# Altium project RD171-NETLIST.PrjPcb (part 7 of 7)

## Sheet 8.SchDoc
size 420 x 297 mm
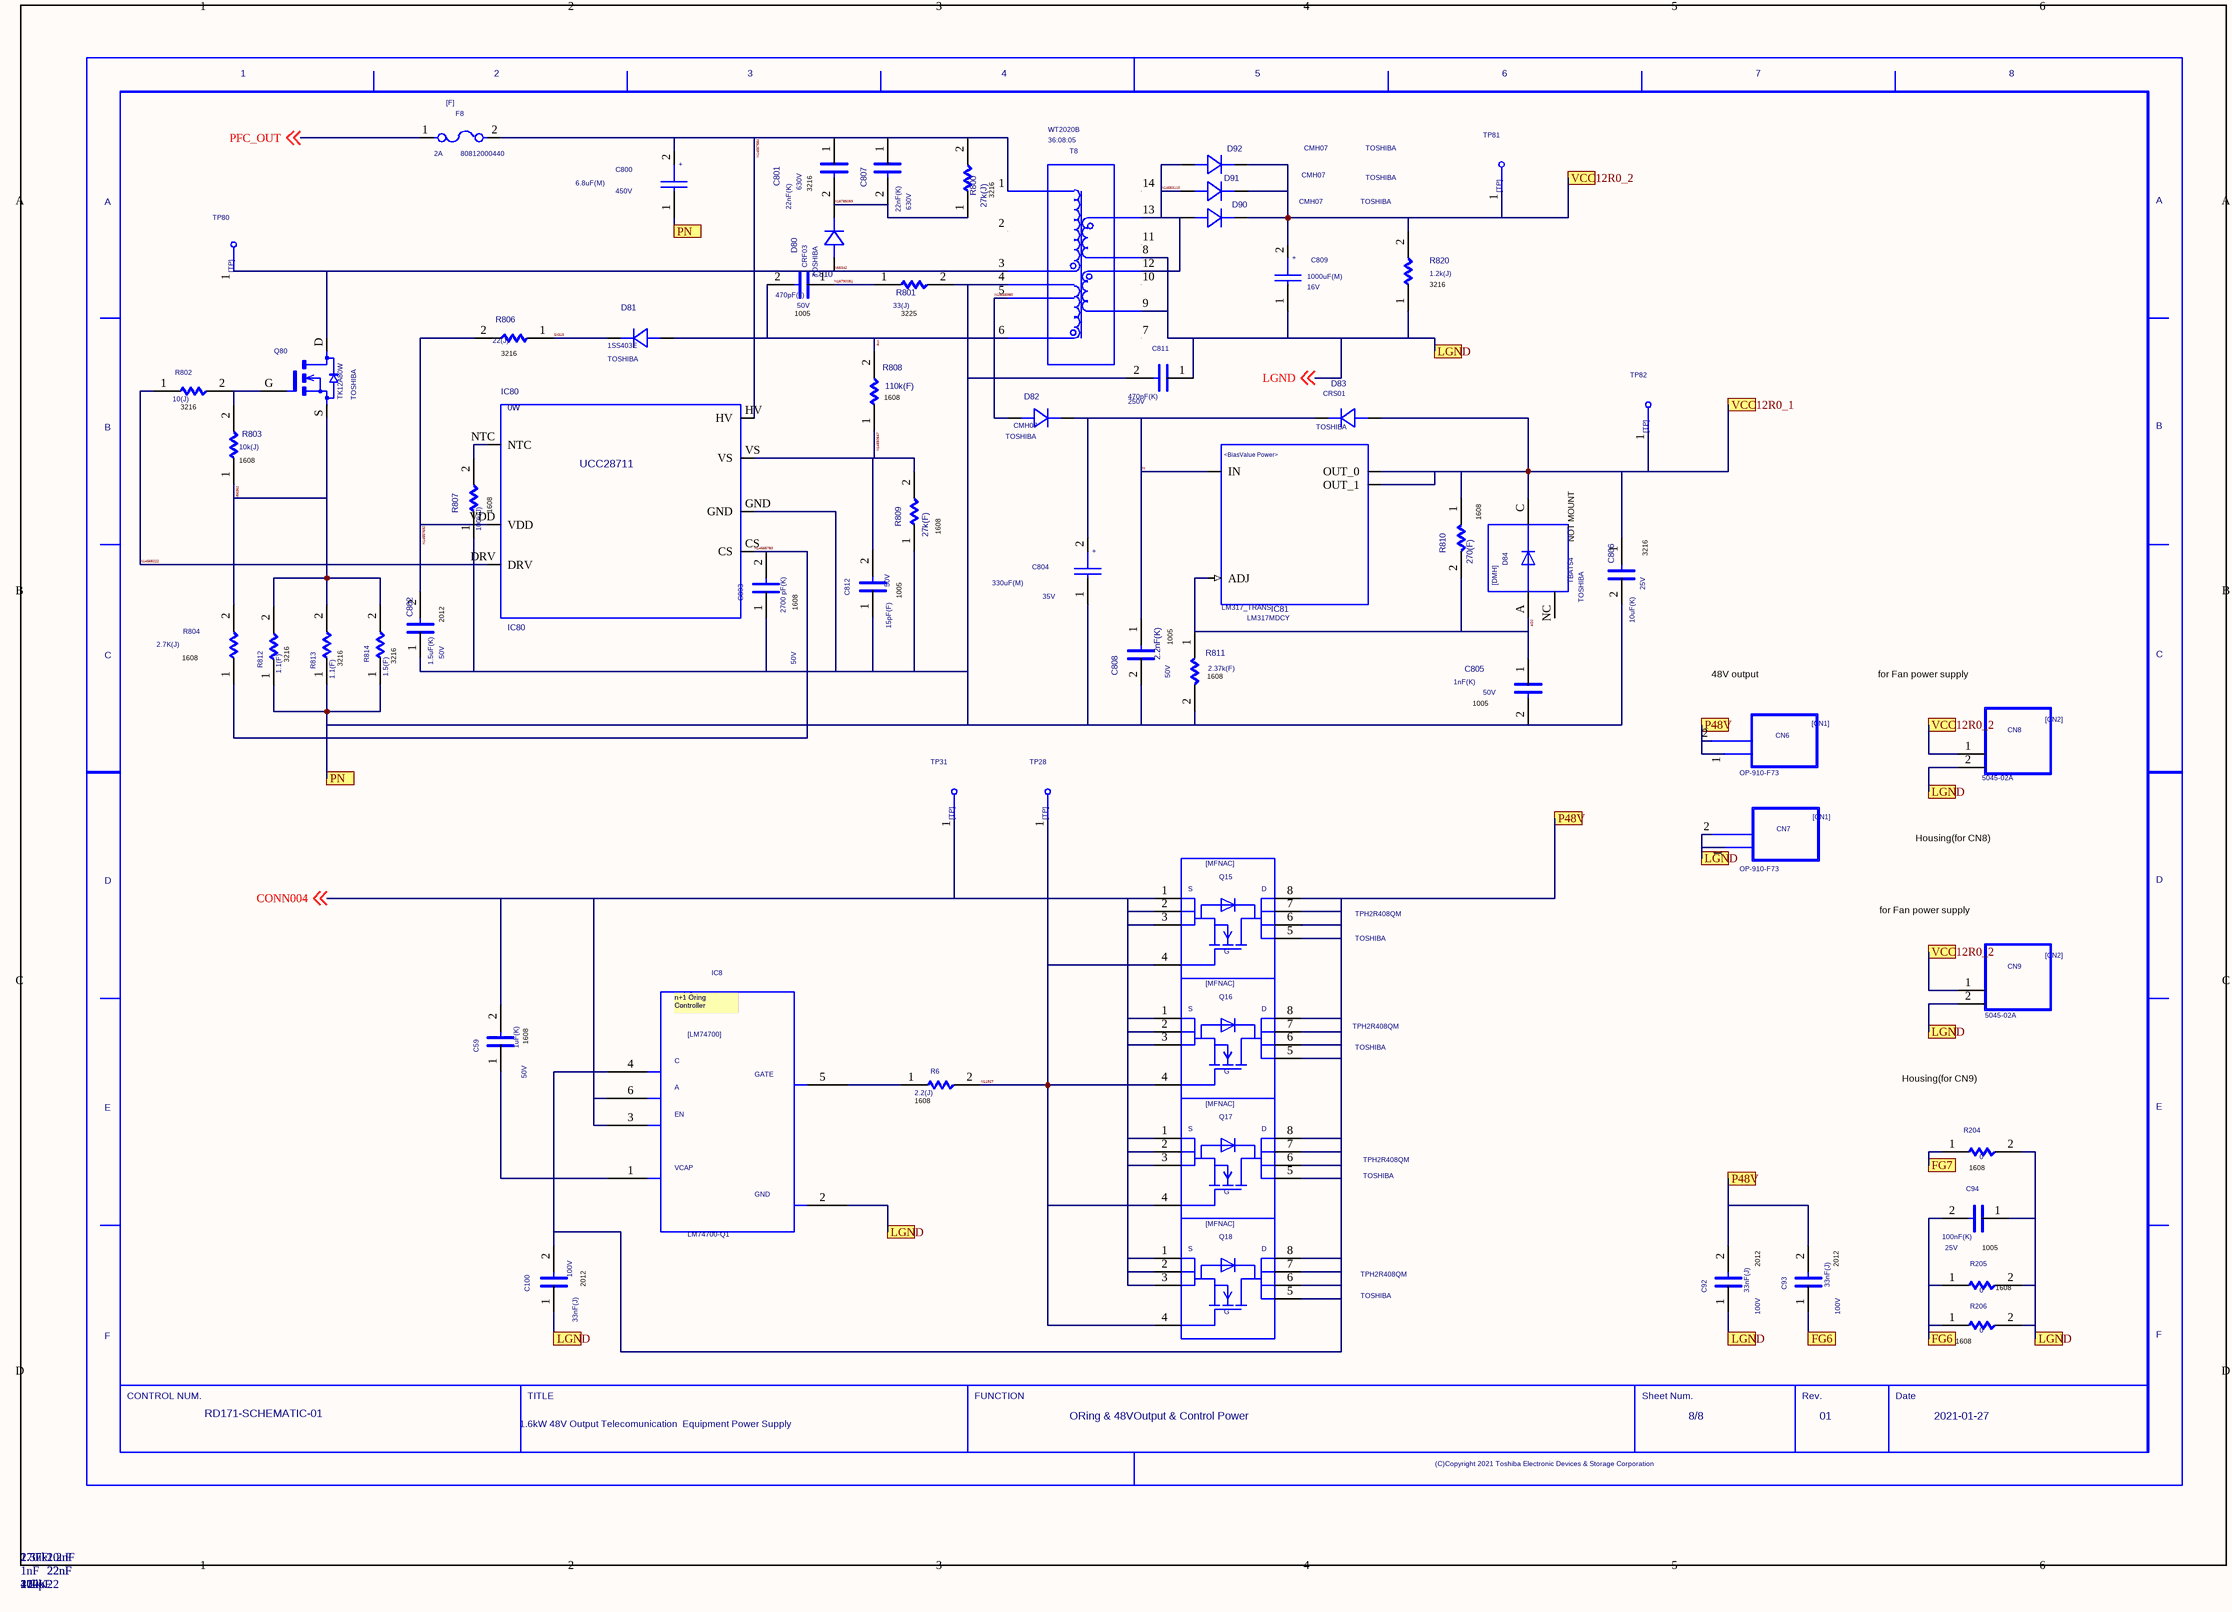
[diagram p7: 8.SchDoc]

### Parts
(Parts that share a designator on the sheet are numbered #1, #2 ... from top to bottom, then left to right.)
C59  VAL2: 50V  VAL1: 1uF(K)  [C1608JB1H105K080AB]  (hidden comment: 1uF)
C92  VAL2: 100V  VAL1: 33nF(J)  [C2012C0G2A333J125AE]  (hidden comment: 33nF)
C93  VAL2: 100V  VAL1: 33nF(J)  [C2012C0G2A333J125AE]  (hidden comment: 33nF)
C94  VAL2: 25V  VAL1: 100nF(K)  (hidden comment: 100nF)
C100  VAL2: 100V  VAL1: 33nF(J)  [C2012C0G2A333J125AE]  (hidden comment: 33nF)
C800  VAL2: 450V  VAL1: 6.8uF(M)  [EKXJ451ETD6R8MJ16S]  (hidden comment: 6.8uF)
C801  VAL2: 630V  VAL1: 22nF(K)  [C3216X7R2J223K130AA]  (hidden comment: 22nF)
C802  VAL2: 50V  VAL1: 1.5uF(K)  [C2012X7R1H155K125AC]  (hidden comment: 1.5uF)
C803  VAL2: 50V  VAL1: 2700 pF(K)  (hidden comment: 2.7nF)
C804  VAL2: 35V  VAL1: 330uF(M)  [EKZH350ETD331MJC5S]  (hidden comment: 330uF)
C805  VAL2: 50V  VAL1: 1nF(K)  (hidden comment: 1nF)
C806  VAL2: 25V  VAL1: 10uF(K)  [C3216X7R1E106K160AE]  (hidden comment: 10uF)
C807  VAL2: 630V  VAL1: 22nF(K)  [C3216X7R2J223K130AA]  (hidden comment: 22nF)
C808  VAL2: 50V  VAL1: 2.2nF(K)  (hidden comment: 2.2nF)
C809  VAL2: 16V  VAL1: 1000uF(M)  [EKZH160ELL102MH20D]  (hidden comment: 1000uF)
C810  VAL2: 50V  VAL1: 470pF(J)  [C1005NP01H471J050BA]  (hidden comment: 470pF)
C811  VAL2: 250V  VAL1: 470pF(K)  [DE2B3SA471KN3AT02F]  (hidden comment: 470pF)
C812  VAL2: 50V  VAL1: 15pF(F)  (hidden comment: NOT MOUNT)
CN6  CN6  [OP-910-F73]  (value not drawn)
CN7  VAL3: OP-910-F73  (hidden comment: CN7)
CN8  CN8  [5045-02A]  (value not drawn)
CN9  CN9  [5045-02A]  (value not drawn)
D80  USERCOMPTEXT3: TOSHIBA  [CRF03]  (hidden comment: D80)
D81  USERCOMPTEXT3: TOSHIBA  [1SS403E]  (hidden comment: D81)
D82  USERCOMPTEXT3: TOSHIBA  [CMH07]  (hidden comment: D82)
D83  USERCOMPTEXT3: TOSHIBA  [CRS01]  (hidden comment: D83)
D84  USERCOMPTEXT3: TOSHIBA  [TBAT54]  (hidden comment: D84)
D90  USERCOMPTEXT3: TOSHIBA  [CMH07]  (hidden comment: D90)
D91  USERCOMPTEXT3: TOSHIBA  [CMH07]  (hidden comment: D91)
D92  USERCOMPTEXT3: TOSHIBA  [CMH07]  (hidden comment: D92)
F8  2A  [80812000440]
IC8  IC8  [LM74700-Q1]  (value not drawn)
IC80  IC80  BIASVALUE POWER: 0W  [UCC28711DR]
IC81  LM317_TRANS  BIASVALUE POWER: <BiasValue Power>  [LM317MDCY]
Q15  USERCOMPTEXT3: TOSHIBA  [TPH2R408QM]  (hidden comment: Q15)
Q16  USERCOMPTEXT3: TOSHIBA  [TPH2R408QM]  (hidden comment: Q16)
Q17  USERCOMPTEXT3: TOSHIBA  [TPH2R408QM]  (hidden comment: Q17)
Q18  USERCOMPTEXT3: TOSHIBA  [TPH2R408QM]  (hidden comment: Q18)
Q80  USERCOMPTEXT3: TOSHIBA  [TK12A80W]  (hidden comment: Q80)
R6  VAL1: 2.2(J)  (hidden comment: 2.2)
R204  0
R205  0
R206  0
R800  VAL1: 27k(J)  [MOS3CT631R273J]  (hidden comment: 27k)
R801  VAL1: 33(J)  [RK73B2ETTD330J]  (hidden comment: 33)
R802  VAL1: 10(J)  (hidden comment: 10)
R803  VAL1: 10k(J)  (hidden comment: 10k)
R804  VAL1: 2.7K(J)  (hidden comment: 2.7k)
R806  VAL1: 22(J)  (hidden comment: 22)
R807  VAL1: 100k(J)  (hidden comment: 100k)
R808  VAL1: 110k(F)  (hidden comment: 110K)
R809  VAL1: 27k(F)  (hidden comment: 27k)
R810  VAL1: 270(F)  (hidden comment: 270)
R811  VAL1: 2.37k(F)  (hidden comment: 2.37k)
R812  VAL1: 1.1(F)  [RK73H2BTTD1R10F]  (hidden comment: 1.1)
R813  VAL1: 1.1(F)  [RK73H2BTTD1R10F]  (hidden comment: 1.1)
R814  VAL1: 1.5(F)  [RK73H2BTTD1R50F]  (hidden comment: 1.5)
R820  VAL1: 1.2k(J)  (hidden comment: 1.2k)
T8  VAL1: 36:08:05  VAL3: WT2020B  (hidden comment: T3_12V67A)
TP28  TP28  [HK-2-S]  (value not drawn)
TP31  TP31  [HK-2-S]  (value not drawn)
TP80  TP80  [HK-2-S]  (value not drawn)
TP81  TP81  [HK-2-S]  (value not drawn)
TP82  TP82  [HK-2-S]  (value not drawn)
U?#8  DATE: 2021-01-27  REVISION: 01  SHEETNUMBER: 8/8  FUNCTION: ORing & 48VOutput & Control Power  TITLE: 1.6kW 48V Output Telecomunication / Equipment Power Supply  DRAWINGNUMBER: RD171-SCHEMATIC-01  (hidden comment: WAKU_DEF100)

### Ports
FG6, FG7, LGND, P48V, PN, VCC12R0_1, VCC12R0_2

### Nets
ADJ: C805.1 D84.A IC81.ADJ R810.2 R811.1
Aux: C810.2 D81.A R808.2 T8.6
CONN004: C59.2 IC8.3 IC8.6 Q15.1 Q15.2 Q15.3 Q16.1 Q16.2 Q16.3 Q17.1 Q17.2 Q17.3 Q18.1 Q18.2 Q18.3 TP31.1 ; off-sheet CONN004
IN: C804.2 C808.1 D82.C D83.C IC81.IN
LGND: C92.1 C94.1 C100.1 C809.1 C811.1 CN7.1 CN7.2 CN8.2 CN9.2 IC8.2 R204.2 R205.2 R206.2 R820.1 T8.8 T8.9 ; off-sheet LGND, port LGND
N11927: Q15.4 Q16.4 Q17.4 Q18.4 R6.2 TP28.1
N66342: D80.A Q80.D T8.3 TP80.1
N66362: Q80.S R803.1 R804.2 R812.2 R813.2 R814.2
N14550647: C812.2 IC80.VS R808.1 R809.2
N14553110: D90.A D91.A D92.A T8.12 T8.13
N14557584: C800.2 C801.1 C807.1 F8.2 IC80.HV R800.2 T8.1
N14557692: C802.2 IC80.VDD R806.2
N14565222: IC80.DRV R802.1
N14565783: C803.2 IC80.CS R804.1
N14565980: D82.A T8.5
N16785059: C801.2 C807.2 D80.C R800.1
N16790081: C810.1 R801.1
PFC_OUT: F8.1 ; off-sheet PFC_OUT
SIG13: D81.C R806.1
SIG136: IC8.5 R6.1
SIG555: C59.1 IC8.1
SIG999: IC80.NTC R807.2
SIG1111: Q80.G R802.2 R803.2
NetC1_1: C800.1 C802.1 C803.1 C804.1 C805.2 C806.2 C808.2 C811.2 C812.1 IC80.GND R801.2 R807.1 R809.1 R811.2 R812.1 R813.1 R814.1 T8.4 ; port PN
NetC70_2: C806.1 D83.A D84.C IC81.OUT_0 IC81.OUT_1 R810.1 TP82.1 ; port VCC12R0_1
NetC92_2: C92.2 C93.2 C100.2 CN6.1 CN6.2 IC8.4 Q15.5 Q15.6 Q15.7 Q15.8 Q16.5 Q16.6 Q16.7 Q16.8 Q17.5 Q17.6 Q17.7 Q17.8 Q18.5 Q18.6 Q18.7 Q18.8 ; port P48V
NetC93_1: C93.1 C94.2 R205.1 R206.1 ; port FG6
NetC809_2: C809.2 CN8.1 CN9.1 D90.C D91.C D92.C R820.2 TP81.1 ; port VCC12R0_2
NetR204_1: R204.1 ; port FG7

Not connected (* = marked no-connect by the designer): D84 NC; T8 2 7 10 11 14

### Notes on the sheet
- 3216
- (near T8) 3216
- (near C810) 1005
- (near R801) 3225
- (near R820) 3216
- (near R806) 3216
- (near R802) 3216
- (near R808) 1608
- (near R803) 1608
- (near IC80) 1608
- (near R810) 1608
- (near R809) 1608
- (near D84) NOT MOUNT
- (near C806) 3216
- (near R804) 1608
- (near R812) 3216
- (near R814) 3216
- (near C802) 2012
- (near C803) 1608
- (near C812) 1005
- 1005
- (near R813) 3216
- (near R811) 1608
- (near C805) 1005
- 48V output
- for Fan power supply
- Housing(for CN8)
  :51191-0200
- (near C59) 1608
- (near R6) 1608
- Housing(for CN9)
  :51191-0200
- (near R204) 1608
- (near C100) 2012
- (near C92) 2012
- (near C93) 2012
- (near R205) 1608
- (near R206) 1608

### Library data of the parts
C59 = C: PARTNAME: Chip1608_GS_1; ORIGINALSYMBOLORIGIN: (0,0); TIME: 16:40:04; UPDATEUSER: t5459927; SAVECOUNT: 1; QUADMODEL: CON_2.2N; FUNCTION: C_C.Normal_package; NOMINALCAPACITA: 2.2n; RATEDVOLTAGE: 50; CDMASTERCADCELG: KC0005; MAKER: TDK; TEMPCHARACTERI2: B; SIZECODESMD: 1608; OUMEMAKER: TYD 太陽誘電; ADSCNVFLAG: ON; ADSCOMPONENTNAME: C_1005; COMP: PRT_52; ADSMODELNAME: s_UMK105BJ222KV_F; PMPRODUCTSTYPEG: HD1-PC1; FNLEADFREETHET1GT2GMCTH1: 2_0_N; CAPACITANCETOLE: K; OUMECLASSIFICATION: セラミックコンデンサ; OUMEMAKERKATAMEI: UMK105BJ222KV-F; INSTANCENAME: INS11769
C92 = C: PARTNAME: Chip2012_GS_1; ORIGINALSYMBOLORIGIN: (0,0); TIME: 16:40:04; UPDATEUSER: t5459927; SAVECOUNT: 1; QUADMODEL: CON_100N; FUNCTION: C_C.Normal_package; NOMINALCAPACITA: 100n; RATEDVOLTAGE: 25; CDMASTERCADCELG: KC0005; MAKER: TDK; SIZECODESMD: 2012; OUMEMAKER: MRT 村田製作所; COMP: PRT_52; ADSMODELNAME: s_GRM155R71E104KE14D; FNLEADFREETHET1GT2GMCTH1: N_N_N; CAPACITANCETOLE: K; OUMECLASSIFICATION: セラミックコンデンサ; OUMEMAKERKATAMEI: GRM155R71E104KE14D; INSTANCENAME: INS11789
C93 = C: PARTNAME: Chip2012_GS_1; ORIGINALSYMBOLORIGIN: (0,0); TIME: 16:40:04; UPDATEUSER: t5459927; SAVECOUNT: 1; QUADMODEL: CON_100N; FUNCTION: C_C.Normal_package; NOMINALCAPACITA: 100n; RATEDVOLTAGE: 25; CDMASTERCADCELG: KC0005; MAKER: TDK; SIZECODESMD: 1005; OUMEMAKER: MRT 村田製作所; COMP: PRT_52; ADSMODELNAME: s_GRM155R71E104KE14D; FNLEADFREETHET1GT2GMCTH1: N_N_N; CAPACITANCETOLE: K; OUMECLASSIFICATION: セラミックコンデンサ; OUMEMAKERKATAMEI: GRM155R71E104KE14D; INSTANCENAME: INS11819
C94 = C: PARTNAME: Chip1005_GS_2; ORIGINALSYMBOLORIGIN: (0,0); TIME: 16:40:04; UPDATEUSER: t5459927; SAVECOUNT: 1; QUADMODEL: CON_100N; FUNCTION: C_C.Normal_package; NOMINALCAPACITA: 100n; RATEDVOLTAGE: 25; CDMASTERCADCELG: KC0005; MAKER: TDK; SIZECODESMD: 1005; OUMEMAKER: MRT 村田製作所; COMP: PRT_52; ADSMODELNAME: s_GRM155R71E104KE14D; FNLEADFREETHET1GT2GMCTH1: N_N_N; VAL3: C1005X7R1E104K050BB; CAPACITANCETOLE: K; OUMECLASSIFICATION: セラミックコンデンサ; OUMEMAKERKATAMEI: GRM155R71E104KE14D; INSTANCENAME: INS11799
C100 = C: PARTNAME: Chip2012_GS_1; ORIGINALSYMBOLORIGIN: (0,0); TIME: 16:40:04; UPDATEUSER: t5459927; SAVECOUNT: 1; QUADMODEL: CON_2.2N; FUNCTION: C_C.Normal_package; NOMINALCAPACITA: 2.2n; RATEDVOLTAGE: 50; CDMASTERCADCELG: KC0005; MAKER: TDK; SIZECODESMD: 2012; OUMEMAKER: MRT 村田製作所; COMP: PRT_52; ADSMODELNAME: s_GRM155R71H222KA01D; PMPRODUCTSTYPEG: HD1; FNLEADFREETHET1GT2GMCTH1: 2_0_N; CAPACITANCETOLE: K; OUMECLASSIFICATION: セラミックコンデンサ; OUMEMAKERKATAMEI: GRM155R71H222KA01D; INSTANCENAME: INS11759
C800 = CP: PARTNAME: EKXJ451E**6R8MJ16S_CC_2; OUMEPARTTYPE: C; UPDATEUSER: t5459927; UPDATETIME: 16:40:04; SAVECOUNT: 1; SAVEAREA0: -1450,-153,20294,13055; ORIGINALSYMBOLORIGIN: (0,0); QUADMODEL: CON_330U; FUNCTION: CP_CP.Normal_package; NOMINALCAPACITA: 330u; RATEDVOLTAGE: 450; CDMASTERCADCELG: DC213N; MAKER: RUBYCON; SIZECODESMD: DIP; OUMEMAKER: SIT ルビコン; COMP: PRT_4; FNLEADFREETHET1GT2GMCTH1: 9_N_N; VAL3: 450MXH330; CAPACITANCETOLE: M; OUMECLASSIFICATION: アルミ電解コンデンサ; OUMEMAKERKATAMEI: 450MXC330M35X40; CHIPSIZE: D35xL30; INSTANCENAME: INS16773428
C801 = C: PARTNAME: Chip3216_GS_1; ORIGINALSYMBOLORIGIN: (0,0); TIME: 16:40:05; UPDATEUSER: t5459927; SAVECOUNT: 1; COMPONENTNAME: C_C; INSTANCENAME: INS14557556; PSPICETEMPLATE: C^@REFDES %1 %2 ?TOLERANCE¦C^@REFDES¦ @VALUE ?IC/IC=@IC/ TC=@TC1,@TC2 ?TOLERANCE¦\n.model C^@REFDES CAP C=1 DEV=@TOLERANCE%¦; SLOPE: CSMAX; VOLTAGE: CMAX; DIST: FLAT; PIN NUMBERS VISIBLE: False; CURRENT: CIMAX; TC2: 0; KNEE: CBMAX; MAX_TEMP: CTMAX
C802 = C: PARTNAME: Chip2012_GS_1; ORIGINALSYMBOLORIGIN: (0,0); TIME: 16:40:05; UPDATEUSER: t5459927; SAVECOUNT: 1; COMPONENTNAME: C_C; INSTANCENAME: INS14557786; PSPICETEMPLATE: C^@REFDES %1 %2 ?TOLERANCE¦C^@REFDES¦ @VALUE ?IC/IC=@IC/ TC=@TC1,@TC2 ?TOLERANCE¦\n.model C^@REFDES CAP C=1 DEV=@TOLERANCE%¦; SLOPE: CSMAX; VOLTAGE: CMAX; DIST: FLAT; PIN NUMBERS VISIBLE: False; CURRENT: CIMAX; TC2: 0; KNEE: CBMAX; MAX_TEMP: CTMAX
C803 = C: PARTNAME: Chip1608_GS_1; ORIGINALSYMBOLORIGIN: (0,0); TIME: 16:40:04; UPDATEUSER: t5459927; SAVECOUNT: 1; NOTMOUNT: NOT MOUNT; QUADMODEL: CON_2.7N; FUNCTION: C_C.Normal_package; NOMINALCAPACITA: 2.7n; RATEDVOLTAGE: 50; CDMASTERCADCELG: DC834K; MAKER: TDK; TEMPCHARACTERI2: B; SIZECODESMD: 1005; OUMEMAKER: TYD 太陽誘電; COMP: PRT_52; ADSMODELNAME: s_UMK105BJ272KV_F; PMPRODUCTSTYPEG: PC1; FNLEADFREETHET1GT2GMCTH1: 3_0_N; VAL3: UMK105BJ272KV-F; CAPACITANCETOLE: K; OUMECLASSIFICATION: セラミックコンデンサ; INSTANCENAME: INS14566383
C804 = CP: PARTNAME: EKZH350E**331MJC5S_CC_3; OUMEPARTTYPE: C; UPDATEUSER: t5459927; UPDATETIME: 16:40:04; SAVECOUNT: 1; SAVEAREA0: -1450,-153,20294,13055; ORIGINALSYMBOLORIGIN: (0,0); QUADMODEL: CON_330U; FUNCTION: CP_CP.Normal_package; NOMINALCAPACITA: 330u; RATEDVOLTAGE: 450; CDMASTERCADCELG: DC213N; MAKER: RUBYCON; SIZECODESMD: DIP; OUMEMAKER: SIT ルビコン; COMP: PRT_4; FNLEADFREETHET1GT2GMCTH1: 9_N_N; VAL3: 450MXH330; CAPACITANCETOLE: M; OUMECLASSIFICATION: アルミ電解コンデンサ; OUMEMAKERKATAMEI: 450MXC330M35X40; CHIPSIZE: D35xL30; INSTANCENAME: INS16773861
C805 = C: PARTNAME: Chip1005_GS_2; ORIGINALSYMBOLORIGIN: (0,0); TIME: 16:40:05; UPDATEUSER: t5459927; SAVECOUNT: 1; COMPONENTNAME: C_C; IC: 0; INSTANCENAME: INS16769854; PSPICETEMPLATE: C^@REFDES %1 %2 ?TOLERANCE¦C^@REFDES¦ @VALUE ?IC/IC=@IC/ ?TOLERANCE¦\n.model C^@REFDES CAP C=1 DEV=@TOLERANCE%¦; SLOPE: CSMAX; VOLTAGE: CMAX; DIST: FLAT; PIN NUMBERS VISIBLE: False; CURRENT: CIMAX; KNEE: CBMAX; MAX_TEMP: CTMAX
C806 = C#1: PARTNAME: Chip3216_GS_1; ORIGINALSYMBOLORIGIN: (0,0); TIME: 16:40:05; UPDATEUSER: t5459927; SAVECOUNT: 1; CaptureCellPackProp: C##1; COMPONENTNAME: C_C; INSTANCENAME: INS16769768; PSPICETEMPLATE: C^@REFDES %1 %2 ?TOLERANCE¦C^@REFDES¦ @VALUE ?IC/IC=@IC/ ?TOLERANCE¦\n.model C^@REFDES CAP C=1 DEV=@TOLERANCE%¦; SLOPE: CSMAX; VOLTAGE: CMAX; DIST: FLAT; PIN NUMBERS VISIBLE: False; CURRENT: CIMAX; KNEE: CBMAX; MAX_TEMP: CTMAX
C807 = C: PARTNAME: Chip3216_GS_1; ORIGINALSYMBOLORIGIN: (0,0); TIME: 16:40:05; UPDATEUSER: t5459927; SAVECOUNT: 1; COMPONENTNAME: C_C; INSTANCENAME: INS16790223; PSPICETEMPLATE: C^@REFDES %1 %2 ?TOLERANCE¦C^@REFDES¦ @VALUE ?IC/IC=@IC/ TC=@TC1,@TC2 ?TOLERANCE¦\n.model C^@REFDES CAP C=1 DEV=@TOLERANCE%¦; SLOPE: CSMAX; VOLTAGE: CMAX; DIST: FLAT; PIN NUMBERS VISIBLE: False; CURRENT: CIMAX; TC2: 0; KNEE: CBMAX; MAX_TEMP: CTMAX
C808 = C#1: PARTNAME: Chip1005_GS_2; ORIGINALSYMBOLORIGIN: (0,0); TIME: 16:40:05; UPDATEUSER: t5459927; SAVECOUNT: 1; CaptureCellPackProp: C##1; NOTMOUNT: NOT MOUNT; COMPONENTNAME: C_C; INSTANCENAME: INS16769784; PSPICETEMPLATE: C^@REFDES %1 %2 ?TOLERANCE¦C^@REFDES¦ @VALUE ?IC/IC=@IC/ ?TOLERANCE¦\n.model C^@REFDES CAP C=1 DEV=@TOLERANCE%¦; SLOPE: CSMAX; VOLTAGE: CMAX; DIST: FLAT; PIN NUMBERS VISIBLE: False; CURRENT: CIMAX; KNEE: CBMAX; MAX_TEMP: CTMAX
C809 = CP: PARTNAME: EKZH160E**102MH20D_CC_1; OUMEPARTTYPE: C; UPDATEUSER: t5459927; UPDATETIME: 16:40:04; SAVECOUNT: 1; SAVEAREA0: -1450,-153,20294,13055; ORIGINALSYMBOLORIGIN: (0,0); QUADMODEL: CON_330U; FUNCTION: CP_CP.Normal_package; NOMINALCAPACITA: 1000u; RATEDVOLTAGE: 16; CDMASTERCADCELG: DC213N; MAKER: NIPPON CHEMI-CON; SIZECODESMD: DIP; OUMEMAKER: SIT ルビコン; COMP: PRT_4; FNLEADFREETHET1GT2GMCTH1: 9_N_N; CAPACITANCETOLE: M; OUMECLASSIFICATION: アルミ電解コンデンサ; CHIPSIZE: D8xL20; INSTANCENAME: INS16773655
C810 = C: PARTNAME: Chip1005_GS_2; ORIGINALSYMBOLORIGIN: (0,0); TIME: 16:40:05; UPDATEUSER: t5459927; SAVECOUNT: 1; COMPONENTNAME: C_C; INSTANCENAME: INS16790089; PSPICETEMPLATE: C^@REFDES %1 %2 ?TOLERANCE¦C^@REFDES¦ @VALUE ?IC/IC=@IC/ TC=@TC1,@TC2 ?TOLERANCE¦\n.model C^@REFDES CAP C=1 DEV=@TOLERANCE%¦; SLOPE: CSMAX; VOLTAGE: CMAX; DIST: FLAT; PIN NUMBERS VISIBLE: False; CURRENT: CIMAX; TC2: 0; KNEE: CBMAX; MAX_TEMP: CTMAX
C811 = C: PARTNAME: DE1B3RA471_GS_1; ORIGINALSYMBOLORIGIN: (0,0); TIME: 16:40:04; UPDATEUSER: t5459927; SAVECOUNT: 1; QUADMODEL: CON_470P; FUNCTION: C_C.Normal_package; NOMINALCAPACITA: 470p; RATEDVOLTAGE: 1K; CDMASTERCADCELG: RD0002; MAKER: MURATA; TEMPCHARACTERI2: B; SIZECODESMD: DIP; OUMEMAKER: MRT 村田製作所; COMP: PRT_50; ADSMODELNAME: s_DE2B3SA471KN3AT02F; FNLEADFREETHET1GT2GMCTH1: 9_1_N; VAL3: DE1B3RA471KA4BN01F; CAPACITANCETOLE: K; OUMECLASSIFICATION: セラミックコンデンサ; INSTANCENAME: INS16997067
C812 = C: PARTNAME: Chip1005_GS_2; ORIGINALSYMBOLORIGIN: (0,0); TIME: 16:40:04; UPDATEUSER: t5459927; SAVECOUNT: 1; NOTMOUNT: NOT MOUNT; QUADMODEL: CON_2.7N; FUNCTION: C_C.Normal_package; NOMINALCAPACITA: 2.7n; RATEDVOLTAGE: 50; CDMASTERCADCELG: DC834K; MAKER: TDK; TEMPCHARACTERI2: B; SIZECODESMD: 1005; OUMEMAKER: TYD 太陽誘電; COMP: PRT_52; ADSMODELNAME: s_UMK105BJ272KV_F; PMPRODUCTSTYPEG: PC1; FNLEADFREETHET1GT2GMCTH1: 3_0_N; VAL3: UMK105BJ272KV-F; CAPACITANCETOLE: K; OUMECLASSIFICATION: セラミックコンデンサ; INSTANCENAME: INS16997896
CN6 = CN1_1: PARTNAME: OP-910_GS; ORIGINALSYMBOLORIGIN: (0,0); TIME: 16:40:05; UPDATEUSER: t5459927; SAVECOUNT: 1; COMP: PRT_38; FUNCTION: CN1_1_CN1_1.Normal_package; MAKER: OSADA; INSTANCENAME: INS17073174
CN7 = CN1_2: PARTNAME: OP-910_GS; ORIGINALSYMBOLORIGIN: (0,0); TIME: 16:40:05; UPDATEUSER: t5459927; SAVECOUNT: 1; COMP: PRT_38; FUNCTION: CN1_2_CN1_2.Normal_package; MAKER: OSADA; INSTANCENAME: INS17073180
CN8 = CN2: PARTNAME: 5045-02A_MX; ORIGINALSYMBOLORIGIN: (0,0); TIME: 16:40:05; UPDATEUSER: t5459927; SAVECOUNT: 1; COMP: PRT_42; FUNCTION: CN2_CN2.Normal_package; MAKER: MOLEX; INSTANCENAME: INS11865
CN9 = CN2: PARTNAME: 5045-02A_MX; ORIGINALSYMBOLORIGIN: (0,0); TIME: 16:40:05; UPDATEUSER: t5459927; SAVECOUNT: 1; COMP: PRT_42; FUNCTION: CN2_CN2.Normal_package; MAKER: MOLEX; INSTANCENAME: INS17018717
D80 = D_D1_0: PARTNAME: CRF03_TS_A; PSPICETEMPLATE: X^@REFDES %1 %2 @MODEL; TIME: 16:40:05; UPDATEUSER: t5459927; SAVECOUNT: 1; OriginalSymbolOrigin: (0,0); COMPONENTNAME: D_D1_0_D_D1_0; BIASVALUE POWER: 0W; INSTANCENAME: INS14557726
D81 = D_D1_0: PARTNAME: 1SS403E_TS_B; PSPICETEMPLATE: X^@REFDES %1 %2 @MODEL; TIME: 16:40:05; UPDATEUSER: t5459927; SAVECOUNT: 1; OriginalSymbolOrigin: (0,0); COMPONENTNAME: D_D1_0_D_D1_0; BIASVALUE POWER: 0W; INSTANCENAME: INS14550497
D82 = D_D1_0: PARTNAME: CMH07_TS_B; PSPICETEMPLATE: X^@REFDES %1 %2 @MODEL; TIME: 16:40:05; UPDATEUSER: t5459927; SAVECOUNT: 1; OriginalSymbolOrigin: (0,0); COMPONENTNAME: D_D1_0_D_D1_0; BIASVALUE POWER: 0W; INSTANCENAME: INS14565946
D83 = D_D_1: PARTNAME: CRS01_TS_B; PSPICETEMPLATE: X^@REFDES %1 %2 @MODEL; TIME: 16:40:05; UPDATEUSER: t5459927; SAVECOUNT: 1; OriginalSymbolOrigin: (0,0); COMPONENTNAME: D_D_1_D_D_1; BIASVALUE POWER: <BiasValue Power>; INSTANCENAME: INS16769596
D84 = DMH: PARTNAME: TBAT54_TS_B; UPDATEUSER: t5459927; UPDATETIME: 16:40:05; SAVECOUNT: 1; SAVEAREA0: -4931,-287,27399,20979; ORIGINALSYMBOLORIGIN: (0,0); NOTMOUNT: NOT MOUNT; COMPONENTNAME: DMH_DMH.Normal_package; COMP: PRT_25; INSTANCENAME: INS16774725
D90 = D_D1_0: PARTNAME: CMH07_TS_B; PSPICETEMPLATE: X^@REFDES %1 %2 @MODEL; TIME: 16:40:05; UPDATEUSER: t5459927; SAVECOUNT: 1; OriginalSymbolOrigin: (0,0); COMPONENTNAME: D_D1_0_D_D1_0; BIASVALUE POWER: 0W; INSTANCENAME: INS687401
D91 = D_D1_0: PARTNAME: CMH07_TS_B; PSPICETEMPLATE: X^@REFDES %1 %2 @MODEL; TIME: 16:40:05; UPDATEUSER: t5459927; SAVECOUNT: 1; OriginalSymbolOrigin: (0,0); COMPONENTNAME: D_D1_0_D_D1_0; BIASVALUE POWER: 0W; INSTANCENAME: INS16791338
D92 = D_D1_0: PARTNAME: CMH07_TS_B; PSPICETEMPLATE: X^@REFDES %1 %2 @MODEL; TIME: 16:40:05; UPDATEUSER: t5459927; SAVECOUNT: 1; OriginalSymbolOrigin: (0,0); COMPONENTNAME: D_D1_0_D_D1_0; BIASVALUE POWER: 0W; INSTANCENAME: INS16791357
F8 = F: PARTNAME: 808****0440_LF; ORIGINALSYMBOLORIGIN: (0,0); TIME: 16:40:04; UPDATEUSER: t5459927; SAVECOUNT: 1; COMP: PRT_21; RATEDINTERRUPTI: 0; FUNCTION: F_F.Normal_package; MOUNTINGFORMSMD: SMD; MAKER: Littelfuse; INSTANCENAME: INS16774494
IC8 = L2412_0: PARTNAME: LM74700-Q1_TI; UPDATEUSER: t5459927; UPDATETIME: 16:40:05; SAVECOUNT: 1; SAVEAREA0: -38879,-46643,67840,2550; ORIGINALSYMBOLORIGIN: (0,0); COMPONENTNAME: L2412_0_L2412_0; COMP: PRT_62; MAKER: TEXAS; INSTANCENAME: INS11539
IC80 = UCC28710_0: PARTNAME: UCC28711D_TI; PSPICETEMPLATE: X^@REFDES %CS %VS %CBC %DRV %VDD %GND %HV @MODEL; TIME: 16:40:05; UPDATEUSER: t5459927; SAVECOUNT: 1; SAVEAREA0: -30042,-41524,74477,2202; OriginalSymbolOrigin: (0,0); COMPONENTNAME: UCC28710_0_UCC28710_0; INSTANCENAME: INS14550599
IC81 = LM317_TRANS_0: ALTERNATE PARTNUMBER: LM317DCY; PARTNAME: LM317MDCY_TI; PARTNUMBER: LM317DCYR; MANUFACTURER: Texas Instruments; PIN_COUNT: 4; SYMBOLCREATER: Altium; DEVICESINPACKAGE: 1; ISHETEROGENEOUS: False; DEVICEDESIGNATOR: A; DEVICENUMBERING: Alpha; PSPICETEMPLATE: X^@REFDES %IN %ADJ %OUT_0 %OUT_1 @MODEL; ORIGINALSYMBOLORIGIN: (0,0); COMPTYPE: IC; TIME: 16:40:05; UPDATEUSER: t5459927; COMPONENTNAME: LM317_TRANS_0_LM317_TRANS_0.Normal_package; INSTANCENAME: INS16769638
Q15 = MFNAC: PARTNAME: TPH2R408QM_TS; UPDATEUSER: t5459927; UPDATETIME: 16:40:05; SAVECOUNT: 1; SAVEAREA0: -10143,-336,37609,28718; ORIGINALSYMBOLORIGIN: (0,0); COMPONENTNAME: MFNAC_MFNAC.Normal_package; COMP: PRT_60; INSTANCENAME: INS11627
Q16 = MFNAC: PARTNAME: TPH2R408QM_TS; UPDATEUSER: t5459927; UPDATETIME: 16:40:05; SAVECOUNT: 1; SAVEAREA0: -10143,-336,37609,28718; ORIGINALSYMBOLORIGIN: (0,0); COMPONENTNAME: MFNAC_MFNAC.Normal_package; COMP: PRT_60; INSTANCENAME: INS11649
Q17 = MFNAC: PARTNAME: TPH2R408QM_TS; UPDATEUSER: t5459927; UPDATETIME: 16:40:05; SAVECOUNT: 1; SAVEAREA0: -10143,-336,37609,28718; ORIGINALSYMBOLORIGIN: (0,0); COMPONENTNAME: MFNAC_MFNAC.Normal_package; COMP: PRT_60; INSTANCENAME: INS11583
Q18 = MFNAC: PARTNAME: TPH2R408QM_TS; UPDATEUSER: t5459927; UPDATETIME: 16:40:05; SAVECOUNT: 1; SAVEAREA0: -10143,-336,37609,28718; ORIGINALSYMBOLORIGIN: (0,0); COMPONENTNAME: MFNAC_MFNAC.Normal_package; COMP: PRT_60; INSTANCENAME: INS11605
Q80 = MFNF_0: PARTNAME: TK12A80W_TS_1; SAVEAREA0: -7027,-292,21786,15988; ORIGINALSYMBOLORIGIN: (0,0); SAVECOUNT: 1; TIME: 16:40:05; UPDATEUSER: t5459927; COMPONENTNAME: MFNF_0_MFNF_0; COMP: PRT_9; INSTANCENAME: INS66344
R6 = R: PARTNAME: Chip1608_GS_1; ORIGINALSYMBOLORIGIN: (0,0); TIME: 16:40:04; UPDATEUSER: t5459927; SAVECOUNT: 1; QUADMODEL: RES_2.2; FUNCTION: R_R.Normal_package; CDMASTERCADCELG: KC0008; MAKER: KAMAYA; RESISTANCETOLER: J; SIZECODESMD: 1608; OUMEMAKER: YGO ヤゲオ; POWERRATING: 100m; MOUNTINGFORMSMD: SMD; COMP: PRT_8; ADSMODELNAME: s_RC0603JR_072R2L; PMPRODUCTSTYPEG: PC1; FNLEADFREETHET1GT2GMCTH1: 2_1_N; VAL3: RMC1/16 - 2R2J TP; VAL2: 100mW; OUMECLASSIFICATION: 表面実装用固定抵抗器; OUMEMAKERKATAMEI: RC0603JR-072R2L; INSTANCENAME: INS11779
R204 = R: PARTNAME: Chip1608_GS_1; ORIGINALSYMBOLORIGIN: (0,0); TIME: 16:40:04; UPDATEUSER: t5459927; SAVECOUNT: 1; QUADMODEL: RES_0; FUNCTION: R_R.Normal_package; CDMASTERCADCELG: KCK0203; MAKER: KOA; RESISTANCETOLER: X; SIZECODESMD: 1608; OUMEMAKER: KOA コーア; POWERRATING: 100m; MOUNTINGFORMSMD: SMD; COMP: PRT_8; ADSMODELNAME: s_RK73Z1JTTD; PMPRODUCTSTYPEG: DME-HD1-PC1; FNLEADFREETHET1GT2GMCTH1: 3_2_N; VAL3: RK73Z1JTTD; VAL2: 100mW; OUMECLASSIFICATION: 表面実装用固定抵抗器; INSTANCENAME: INS11829
R205 = R: PARTNAME: Chip1608_GS_1; ORIGINALSYMBOLORIGIN: (0,0); TIME: 16:40:04; UPDATEUSER: t5459927; SAVECOUNT: 1; QUADMODEL: RES_0; FUNCTION: R_R.Normal_package; CDMASTERCADCELG: KCK0203; MAKER: KOA; RESISTANCETOLER: X; SIZECODESMD: 1608; OUMEMAKER: KOA コーア; POWERRATING: 100m; MOUNTINGFORMSMD: SMD; COMP: PRT_8; ADSMODELNAME: s_RK73Z1JTTD; PMPRODUCTSTYPEG: DME-HD1-PC1; FNLEADFREETHET1GT2GMCTH1: 3_2_N; VAL3: RK73Z1JTTD; VAL2: 100mW; OUMECLASSIFICATION: 表面実装用固定抵抗器; INSTANCENAME: INS11809
R206 = R: PARTNAME: Chip1608_GS_1; ORIGINALSYMBOLORIGIN: (0,0); TIME: 16:40:04; UPDATEUSER: t5459927; SAVECOUNT: 1; QUADMODEL: RES_0; FUNCTION: R_R.Normal_package; CDMASTERCADCELG: KCK0203; MAKER: KOA; RESISTANCETOLER: X; SIZECODESMD: 1608; OUMEMAKER: KOA コーア; POWERRATING: 100m; MOUNTINGFORMSMD: SMD; COMP: PRT_8; ADSMODELNAME: s_RK73Z1JTTD; PMPRODUCTSTYPEG: DME-HD1-PC1; FNLEADFREETHET1GT2GMCTH1: 3_2_N; VAL3: RK73Z1JTTD; VAL2: 100mW; OUMECLASSIFICATION: 表面実装用固定抵抗器; INSTANCENAME: INS11839
R800 = R: PARTNAME: MOS3C_KO; ORIGINALSYMBOLORIGIN: (0,0); TIME: 16:40:05; UPDATEUSER: t5459927; SAVECOUNT: 1; VAL2: 3w; COMPONENTNAME: R_R; BIASVALUE POWER: 0W; INSTANCENAME: INS14550461; POWER: RMAX; PSPICETEMPLATE: R^@REFDES %1 %2 ?TOLERANCE¦R^@REFDES¦ @VALUE TC=@TC1,@TC2 ?TOLERANCE¦\n.model R^@REFDES RES R=1 DEV=@TOLERANCE%¦; SLOPE: RSMAX; VOLTAGE: RVMAX; DIST: FLAT; PIN NUMBERS VISIBLE: False; TC2: 0; MAX_TEMP: RTMAX
R801 = R: PARTNAME: Chip3225_GS_1; ORIGINALSYMBOLORIGIN: (0,0); TIME: 16:40:04; UPDATEUSER: t5459927; SAVECOUNT: 1; QUADMODEL: RES_2.2; FUNCTION: R_R.Normal_package; CDMASTERCADCELG: KC0008; MAKER: KAMAYA; RESISTANCETOLER: J; SIZECODESMD: 1608; OUMEMAKER: YGO ヤゲオ; POWERRATING: 100m; MOUNTINGFORMSMD: SMD; NOMINALRESISTAN: 2.2; COMP: PRT_8; ADSMODELNAME: s_RC0603JR_072R2L; PMPRODUCTSTYPEG: PC1; FNLEADFREETHET1GT2GMCTH1: 2_1_N; VAL3: RMC1/16 - 2R2J TP; VAL2: 100mW,±5%; OUMECLASSIFICATION: 表面実装用固定抵抗器; OUMEMAKERKATAMEI: RC0603JR-072R2L; INSTANCENAME: INS16790038
R802 = R: PARTNAME: Chip3216_GS_1; ORIGINALSYMBOLORIGIN: (0,0); TIME: 16:40:04; UPDATEUSER: t5459927; SAVECOUNT: 1; QUADMODEL: RES_2.2; FUNCTION: R_R.Normal_package; CDMASTERCADCELG: KC0008; MAKER: KAMAYA; RESISTANCETOLER: J; SIZECODESMD: 1608; OUMEMAKER: YGO ヤゲオ; POWERRATING: 100m; MOUNTINGFORMSMD: SMD; NOMINALRESISTAN: 2.2; COMP: PRT_8; ADSMODELNAME: s_RC0603JR_072R2L; PMPRODUCTSTYPEG: PC1; FNLEADFREETHET1GT2GMCTH1: 2_1_N; VAL3: RMC1/16 - 2R2J TP; VAL2: 100mW,±5%; OUMECLASSIFICATION: 表面実装用固定抵抗器; OUMEMAKERKATAMEI: RC0603JR-072R2L; INSTANCENAME: INS14565241
R803 = R: PARTNAME: Chip1608_GS_1; ORIGINALSYMBOLORIGIN: (0,0); TIME: 16:40:05; UPDATEUSER: t5459927; SAVECOUNT: 1; COMPONENTNAME: R_R; BIASVALUE POWER: 0W; INSTANCENAME: INS14552964; POWER: RMAX; PSPICETEMPLATE: R^@REFDES %1 %2 ?TOLERANCE¦R^@REFDES¦ @VALUE TC=@TC1,@TC2 ?TOLERANCE¦\n.model R^@REFDES RES R=1 DEV=@TOLERANCE%¦; SLOPE: RSMAX; VOLTAGE: RVMAX; DIST: FLAT; PIN NUMBERS VISIBLE: False; TC2: 0; MAX_TEMP: RTMAX
R804 = R: PARTNAME: Chip1608_GS_1; ORIGINALSYMBOLORIGIN: (0,0); TIME: 16:40:04; UPDATEUSER: t5459927; SAVECOUNT: 1; QUADMODEL: RES_10K; FUNCTION: R_R.Normal_package; CDMASTERCADCELG: KC0133; MAKER: KOA; RESISTANCETOLER: J; SIZECODESMD: 1608; OUMEMAKER: KOA コーア; POWERRATING: 100m; MOUNTINGFORMSMD: SMD; COMP: PRT_8; ADSMODELNAME: s_RK73B1JTTD272J@@; FNLEADFREETHET1GT2GMCTH1: N_N_N; VAL3: RK73B1JTTD272J; VAL2: 100mW,±5%; OUMECLASSIFICATION: 表面実装用固定抵抗器; OUMEMAKERKATAMEI: RK73B1JTTD272J@@; INSTANCENAME: INS14565500
R806 = R: PARTNAME: Chip3216_GS_1; ORIGINALSYMBOLORIGIN: (0,0); TIME: 16:40:05; UPDATEUSER: t5459927; SAVECOUNT: 1; COMPONENTNAME: R_R; BIASVALUE POWER: 0W; INSTANCENAME: INS14550549; POWER: RMAX; PSPICETEMPLATE: R^@REFDES %1 %2 ?TOLERANCE¦R^@REFDES¦ @VALUE TC=@TC1,@TC2 ?TOLERANCE¦\n.model R^@REFDES RES R=1 DEV=@TOLERANCE%¦; SLOPE: RSMAX; VOLTAGE: RVMAX; DIST: FLAT; PIN NUMBERS VISIBLE: False; TC2: 0; MAX_TEMP: RTMAX
R807 = R: PARTNAME: Chip1608_GS_1; ORIGINALSYMBOLORIGIN: (0,0); TIME: 16:40:05; UPDATEUSER: t5459927; SAVECOUNT: 1; COMPONENTNAME: R_R; BIASVALUE POWER: 0W; INSTANCENAME: INS14550861; POWER: RMAX; PSPICETEMPLATE: R^@REFDES %1 %2 ?TOLERANCE¦R^@REFDES¦ @VALUE TC=@TC1,@TC2 ?TOLERANCE¦\n.model R^@REFDES RES R=1 DEV=@TOLERANCE%¦; SLOPE: RSMAX; VOLTAGE: RVMAX; DIST: FLAT; PIN NUMBERS VISIBLE: False; TC2: 0; MAX_TEMP: RTMAX
R808 = R: PARTNAME: Chip1608_GS_1; ORIGINALSYMBOLORIGIN: (0,0); TIME: 16:40:05; UPDATEUSER: t5459927; SAVECOUNT: 1; COMPONENTNAME: R_R; BIASVALUE POWER: 0W; INSTANCENAME: INS14550571; POWER: RMAX; PSPICETEMPLATE: R^@REFDES %1 %2 ?TOLERANCE¦R^@REFDES¦ @VALUE TC=@TC1,@TC2 ?TOLERANCE¦\n.model R^@REFDES RES R=1 DEV=@TOLERANCE%¦; SLOPE: RSMAX; VOLTAGE: RVMAX; DIST: FLAT; PIN NUMBERS VISIBLE: False; TC2: 0; MAX_TEMP: RTMAX
R809 = R: PARTNAME: Chip1608_GS_1; ORIGINALSYMBOLORIGIN: (0,0); TIME: 16:40:05; UPDATEUSER: t5459927; SAVECOUNT: 1; COMPONENTNAME: R_R; BIASVALUE POWER: 0W; INSTANCENAME: INS14550671; POWER: RMAX; PSPICETEMPLATE: R^@REFDES %1 %2 ?TOLERANCE¦R^@REFDES¦ @VALUE TC=@TC1,@TC2 ?TOLERANCE¦\n.model R^@REFDES RES R=1 DEV=@TOLERANCE%¦; SLOPE: RSMAX; VOLTAGE: RVMAX; DIST: FLAT; PIN NUMBERS VISIBLE: False; TC2: 0; MAX_TEMP: RTMAX
R810 = R: PARTNAME: Chip1608_GS_1; ORIGINALSYMBOLORIGIN: (0,0); TIME: 16:40:05; UPDATEUSER: t5459927; SAVECOUNT: 1; COMPONENTNAME: R_R; INSTANCENAME: INS16769736; POWER: RMAX; PSPICETEMPLATE: R^@REFDES %1 %2 ?TOLERANCE¦R^@REFDES¦ @VALUE TC=@TC1,@TC2 ?TOLERANCE¦\n.model R^@REFDES RES R=1 DEV=@TOLERANCE%¦; SLOPE: RSMAX; VOLTAGE: RVMAX; DIST: FLAT; PIN NUMBERS VISIBLE: False; TC2: 0; MAX_TEMP: RTMAX
R811 = R: PARTNAME: Chip1608_GS_1; ORIGINALSYMBOLORIGIN: (0,0); TIME: 16:40:05; UPDATEUSER: t5459927; SAVECOUNT: 1; COMPONENTNAME: R_R; INSTANCENAME: INS16769832; POWER: RMAX; PSPICETEMPLATE: R^@REFDES %1 %2 ?TOLERANCE¦R^@REFDES¦ @VALUE TC=@TC1,@TC2 ?TOLERANCE¦\n.model R^@REFDES RES R=1 DEV=@TOLERANCE%¦; SLOPE: RSMAX; VOLTAGE: RVMAX; DIST: FLAT; PIN NUMBERS VISIBLE: False; TC2: 0; MAX_TEMP: RTMAX
R812 = R: PARTNAME: Chip3216_GS_1; ORIGINALSYMBOLORIGIN: (0,0); TIME: 16:40:04; UPDATEUSER: t5459927; SAVECOUNT: 1; QUADMODEL: RES_3.3; FUNCTION: R_R.Normal_package; CDMASTERCADCELG: KC0014; MAKER: VISHAY; RESISTANCETOLER: J; SIZECODESMD: 3216; OUMEMAKER: NAE パナソニックエレクトロニックデバイス; POWERRATING: 250m; MOUNTINGFORMSMD: SMD; NOMINALRESISTAN: 3.3; COMP: PRT_5; ADSMODELNAME: s_ERJ8GEYJ3R3V; FNLEADFREETHET1GT2GMCTH1: N_N_N; VAL3: CRCW12063R01FKEAHP; VAL2: 500mW,±1%; OUMECLASSIFICATION: 表面実装用固定抵抗器; OUMEMAKERKATAMEI: ERJ8GEYJ3R3V; INSTANCENAME: INS16790614
R813 = R: PARTNAME: Chip3216_GS_1; ORIGINALSYMBOLORIGIN: (0,0); TIME: 16:40:04; UPDATEUSER: t5459927; SAVECOUNT: 1; QUADMODEL: RES_3.3; FUNCTION: R_R.Normal_package; CDMASTERCADCELG: KC0014; MAKER: VISHAY; RESISTANCETOLER: J; SIZECODESMD: 3216; OUMEMAKER: NAE パナソニックエレクトロニックデバイス; POWERRATING: 250m; MOUNTINGFORMSMD: SMD; NOMINALRESISTAN: 3.3; COMP: PRT_5; ADSMODELNAME: s_ERJ8GEYJ3R3V; FNLEADFREETHET1GT2GMCTH1: N_N_N; VAL3: CRCW12063R01FKEAHP; VAL2: 500mW,±1%; OUMECLASSIFICATION: 表面実装用固定抵抗器; OUMEMAKERKATAMEI: ERJ8GEYJ3R3V; INSTANCENAME: INS14565352
R814 = R: PARTNAME: Chip3216_GS_1; ORIGINALSYMBOLORIGIN: (0,0); TIME: 16:40:04; UPDATEUSER: t5459927; SAVECOUNT: 1; QUADMODEL: RES_3.3; FUNCTION: R_R.Normal_package; CDMASTERCADCELG: KC0014; MAKER: KOA; RESISTANCETOLER: J; SIZECODESMD: 3216; POWERRATING: 250m; MOUNTINGFORMSMD: SMD; NOMINALRESISTAN: 3.3; COMP: PRT_5; ADSMODELNAME: s_RK73H2BTTD1R50F; FNLEADFREETHET1GT2GMCTH1: N_N_N; VAL2: 250mW,±1%; OUMECLASSIFICATION: 表面実装用固定抵抗器; INSTANCENAME: INS16790603
R820 = R: PARTNAME: Chip3216_GS_1; ORIGINALSYMBOLORIGIN: (0,0); TIME: 16:40:05; UPDATEUSER: t5459927; SAVECOUNT: 1; VAL2: 250mW; COMPONENTNAME: R_R; BIASVALUE POWER: 0W; INSTANCENAME: INS687465; POWER: RMAX; PSPICETEMPLATE: R^@REFDES %1 %2 ?TOLERANCE¦R^@REFDES¦ @VALUE TC=@TC1,@TC2 ?TOLERANCE¦\n.model R^@REFDES RES R=1 DEV=@TOLERANCE%¦; SLOPE: RSMAX; VOLTAGE: RVMAX; DIST: FLAT; PIN NUMBERS VISIBLE: False; TC2: 0; MAX_TEMP: RTMAX
T8 = T3_14: PARTNAME: WT2020_GS; UPDATEUSER: t5459927; UPDATETIME: 14:07:07; SAVECOUNT: 2; TIME: 16:40:06; SAVEAREA0: -40003,-38869,48929,2125; ORIGINALSYMBOLORIGIN: (-7620,0)
TP28 = TP: PARTNAME: HK-2_M8; UPDATEUSER: t5459927; UPDATETIME: 16:40:05; SAVECOUNT: 1; SAVEAREA0: -242,-92,12810,7836; ORIGINALSYMBOLORIGIN: (0,0); COMP: PRT_44; FUNCTION: TP_TP.Normal_package; MAKER: MAC8; INSTANCENAME: INS11849
TP31 = TP: PARTNAME: HK-2_M8; UPDATEUSER: t5459927; UPDATETIME: 16:40:05; SAVECOUNT: 1; SAVEAREA0: -242,-92,12810,7836; ORIGINALSYMBOLORIGIN: (0,0); COMP: PRT_44; FUNCTION: TP_TP.Normal_package; MAKER: MAC8; INSTANCENAME: INS11857
TP80 = TP: PARTNAME: HK-2_M8; UPDATEUSER: t5459927; UPDATETIME: 16:40:05; SAVECOUNT: 1; SAVEAREA0: -242,-92,12810,7836; ORIGINALSYMBOLORIGIN: (0,0); COMP: PRT_44; FUNCTION: TP_TP.Normal_package; MAKER: MAC8; INSTANCENAME: INS16775798
TP81 = TP: PARTNAME: HK-2_M8; UPDATEUSER: t5459927; UPDATETIME: 16:40:05; SAVECOUNT: 1; SAVEAREA0: -242,-92,12810,7836; ORIGINALSYMBOLORIGIN: (0,0); COMP: PRT_44; FUNCTION: TP_TP.Normal_package; MAKER: MAC8; INSTANCENAME: INS16775838
TP82 = TP: PARTNAME: HK-2_M8; UPDATEUSER: t5459927; UPDATETIME: 16:40:05; SAVECOUNT: 1; SAVEAREA0: -242,-92,12810,7836; ORIGINALSYMBOLORIGIN: (0,0); COMP: PRT_44; FUNCTION: TP_TP.Normal_package; MAKER: MAC8; INSTANCENAME: INS16775922
U?#8 = WAKU_DEF100: PLOTTIME: HH:MM; SAVEAREA0: 168739,-66042,466246,90057; TIME: 14:30:25; UPDATEUSER: t5459927; UPDATETIME: 15:16:58; SAVECOUNT: 5; OriginalSymbolOrigin: (10160,284480)

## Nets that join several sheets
CONN002: 4 (6 pins), 5 (T5.1 T6.1)
CONN003: 4 (D18.C D19.A L3.2), 5 (T5.6 T6.6)
CONN004: 5 (18 pins), 6 (R75.2), 8 (16 pins)
CS: 4 (D14.C), 6 (R67.2 R185.2)
CSA: 2 (5 pins), 3 (R170.1)
CSB: 2 (5 pins), 3 (R169.1)
GDA: 2 (C81.2 IC2.2), 3 (IC3.14 TP5.1)
GDB: 2 (C80.2 IC2.4), 3 (IC3.17 TP6.1)
LGND: 1 (R805.1), 4 (R9.1 T4.3), 5 (61 pins), 6 (29 pins), 7 (R194.2 R195.2 R196.2 R197.2), 8 (16 pins)
NetC1_1: 1 (5 pins), 2 (21 pins), 3 (34 pins), 4 (23 pins), 7 (28 pins), 8 (18 pins)
NetC70_2: 1 (C70.2 D48.C IC20.1), 2 (5 pins), 3 (R116.1 R120.1), 4 (R122.1 R123.1), 8 (7 pins)
NetC95_2: 3 (R117.2), 7 (16 pins)
NetC809_2: 5 (R124.1 R125.1), 6 (R49.1), 8 (8 pins)
OUTA1: 4 (R111.1), 7 (IC21.4 R187.2)
OUTA2: 6 (IC10.22), 7 (R149.2)
OUTB1: 4 (R110.1), 7 (IC22.4 R189.2)
OUTB2: 6 (IC10.21), 7 (R150.2)
OUTC1: 4 (R113.1), 7 (IC23.4 R191.2)
OUTC2: 6 (IC10.20), 7 (R151.2)
OUTD1: 4 (R112.1), 7 (IC24.4 R193.2)
OUTD2: 6 (IC10.19), 7 (R152.2)
OUTE: 5 (IC6.2 IC7.2 TP25.1), 6 (IC10.18)
OUTF: 5 (IC6.4 IC7.4 TP24.1), 6 (IC10.17)
PFC_OUT: 2 (6 pins), 3 (R92.2), 4 (R178.2 T4.2), 8 (F8.1)
PFC_VIN: 2 (D8.C D9.C), 3 (R95.2)
SIG6: 1 (C33.1 C63.2 C65.1 L12.4), 2 (D3.3 D9.A L2.1)
SIG8: 1 (C33.2 C65.2 IC20.3 R138.2), 2 (D3.2 D8.A L1.1)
